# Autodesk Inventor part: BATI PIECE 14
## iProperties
Created: 2004-11
Part Number: BATI PIECE 14
Document SubType Name: Modeling
Designer: Bruno
Manufacturer: Standard
Standards Organization: Custom
Author: Bruno
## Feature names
1. Base1
